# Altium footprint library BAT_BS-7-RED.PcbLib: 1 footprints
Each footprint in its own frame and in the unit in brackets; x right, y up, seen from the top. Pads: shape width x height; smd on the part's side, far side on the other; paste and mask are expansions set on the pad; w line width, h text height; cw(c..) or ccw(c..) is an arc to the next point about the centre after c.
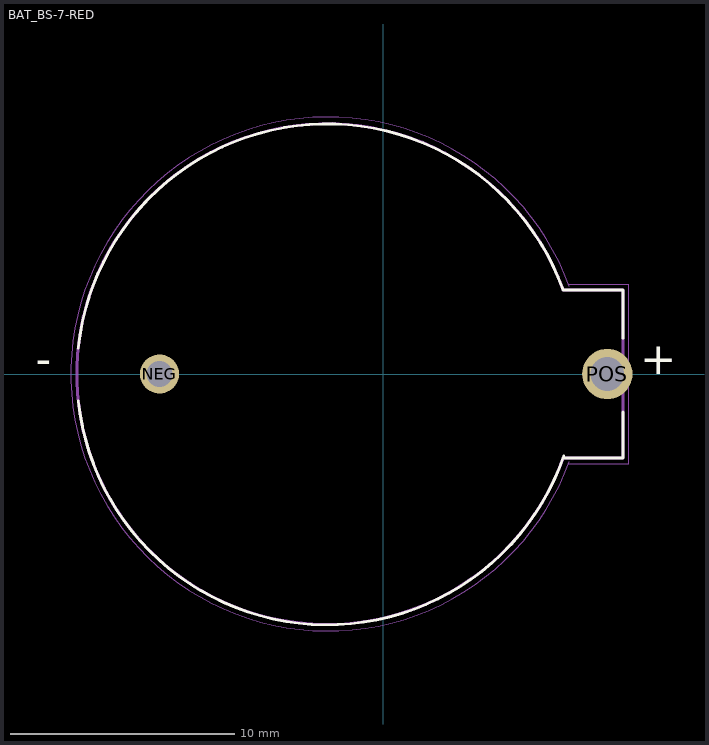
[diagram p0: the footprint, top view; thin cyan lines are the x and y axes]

## BAT_BS-7-RED [mm]
pads (2):
  round 1.755 hole 1.17: NEG(-10,0)
  round 2.25 hole 1.5: POS(10,0)
Top Overlay:
  lines w0.127: -13.633,1.155 cw(c-2.509,-0.014) 8.002,3.811 ; -13.629,-1.194 ccw(c-2.514,-0.026) 8.054,-3.664 ; 8.024,-3.75 10.699,-3.75 10.7,-1.7 ; 8.024,3.75 10.7,3.75 10.7,1.6
  text "+" at 11.474,0 h1.42
  text "-" at -15.526,0 h1.42
Mechanical 13:
  lines w0.127: 7.997,-3.825 cw(c-2.513,0) 7.997,3.825 ; 8.024,-3.75 10.699,-3.75 10.699,3.75 8.024,3.75
  text "+" at 11.474,0 h1.42
  text "-" at -15.526,0 h1.42
Mechanical 15:
  lines w0.05: 8.274,-4 10.949,-4 10.949,4 8.274,4 ; 8.301,-3.926 cw(c-2.485,0) 8.301,3.926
